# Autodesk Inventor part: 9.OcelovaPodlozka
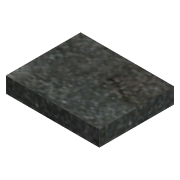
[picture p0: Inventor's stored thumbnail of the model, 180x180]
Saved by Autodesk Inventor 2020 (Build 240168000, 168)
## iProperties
Created: 2022-02
Part Number: 9.OcelovaPodlozka
Material: Steel
Document SubType Name: Modeling
Designer: marti
Density: 7.85 g/cm^3
Appearance: Plate
Mass: 28.26 g
Surface Area: 19.8 cm^2
Volume: 3.6 cm^3
Author: marti
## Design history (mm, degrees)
sketch "Sketch1"
  geometry: L1 (15, 12)-(-15, 12); L2 (-15, 12)-(-15, -12); L3 (-15, -12)-(15, -12); L4 (15, -12)-(15, 12); L5 (15, 12)-(-15, -12); L6 (-15, 12)-(15, -12); 1 further point
  constraints: 12 end point, 2 midpoint, 2 parallel, 1 horizontal, 1 perpendicular
  dimensions: "d0" = 30 distance of L3.end L2.end; "d1" = 24 distance of L2.end L1.end
extrude "Extrusion1" new body sketch "Sketch1" distance "d2" = 5; taper "d3" = 0 deg
body "Solid1"
